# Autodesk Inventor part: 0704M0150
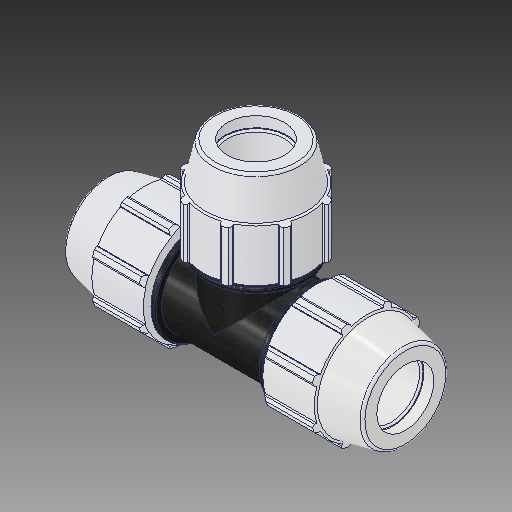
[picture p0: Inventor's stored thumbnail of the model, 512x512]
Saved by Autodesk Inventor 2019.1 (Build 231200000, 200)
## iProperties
Created: 2017-02
Part Number: 0704M0150
Material: PVC-Piping
Description: PLASSON TEE 1 1/2'' - 1 1/2'' - 1 1/2''
Document SubType Name: Modeling
Designer: KIM
Mass: 92.6774 g
Surface Area: 199.44 cm^2
Volume: 66.1981 cm^3
Density: 1.4 g/cm^3
Appearance: PTFE
Author: KIM
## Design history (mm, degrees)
derived "0704M0.ipt"
feature "Solid1::0704M0.ipt"
tag "TaggingFeature1"
body "Solid1"
other parameters: "d_" = 48.1, "E_" = 96.012, "A_" = 125.984, "l_" = 94.996, "H_" = 251.968, "d2" = 48.1, "d4" = 10.49867, "d5" = 31.496, "d7" = 96.012, "d11" = 4.19947, "d13" = 120 deg, "d14" = 72.15, "d15" = 12 deg, "d16" = 83.53044, "d18" = 2.405, "d19" = 35 deg, "d20" = 17.5 deg, "d21" = 89.29116, "d23" = 0, "d25" = 360 deg, "d27" = 1.92024, "d33" = 0.962, "d42" = 44.0944, "d43" = 2.88036, "d46" = 1.443, "d63" = 94.996, "d67" = 72.009, "d76" = 48.1, "d77" = 96.012, "d78" = 12 deg, "d79" = 125.984, "d80" = 120 deg, "d81" = 72.15, "d82" = 10.49867, "d85" = 72.009, "d86" = 83.53044, "d87" = 4.19947, "d88" = 4.19947, "d89" = 31.496, "d90" = 44.0944, "d96" = 12.5984, "d98" = 89.29116, "d99" = 35 deg, "d100" = 17.5 deg, "d102" = 0, "d103" = 1.92024, "d107" = 360 deg, "d109" = 1.443, "d112" = 2.405, "d118" = 360 deg, "d121" = 0, "d128" = 251.968, "d131" = 43.29, "d132" = 43.29, "d133" = 94.996, "d134" = 1.89992, "d135" = 12.5984, "d152" = 0, "d154" = 0, "d156" = 0, "d158" = 0
